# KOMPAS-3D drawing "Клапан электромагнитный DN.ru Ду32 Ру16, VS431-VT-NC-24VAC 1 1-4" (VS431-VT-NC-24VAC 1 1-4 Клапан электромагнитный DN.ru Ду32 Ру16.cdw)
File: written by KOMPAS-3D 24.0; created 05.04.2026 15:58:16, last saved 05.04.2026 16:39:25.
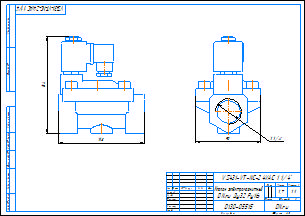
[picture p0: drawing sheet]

Document properties: c3d_UniqueCompID: ef56311e-7521-43dc-8291-0e6108b3d81d; Автор: artio; Класс точности: c; Знак неуказанной шероховатости: Шероховатость не задана; Рассекать на разрезах: Да; c3d_UniqueCompID: ef56311e-7521-43dc-8291-0e6108b3d81d; Автор: artio; Класс точности: c; Знак неуказанной шероховатости: Шероховатость не задана; Рассекать на разрезах: Да; c3d_UniqueCompID: ef56311e-7521-43dc-8291-0e6108b3d81d; Автор: artio; Класс точности: c; Знак неуказанной шероховатости: Шероховатость не задана; Рассекать на разрезах: Да; Автор: artio; Форматы листов документа: A3; Полное имя файла: VS431-VT-NC-24VAC 1 1-4 Клапан электромагнитный DN.ru Ду32 Ру16.m3d; Масса: 1.701; Наименование: Клапан электромагнитный DN.ru Ду32 Ру16; Количество листов документа: 1; Примечание: D130-05515

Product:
- Body: Тело 1  | qty 1
    Масса: 3.709873
- Part/product: Клапан электромагнитный DN.ru Ду32 Ру16  | designation VS431-VT-NC-24VAC 1 1-4
    Масса: 1.701
    Раздел спецификации: Прочие изделия
    Примечание: D130-05515
    additional columns: ef56311e-7521-43dc-8291-0e6108b3d81d; artio; c; Шероховатость не задана; Да

Views: Вид 1, Спереди
Referenced files in C:\Users\artio\OneDrive\Рабочий стол\Клапан электромагнитный DN.ru\VS431\VS431-ET-NC\: VS431-ET-NC-24VAC 3-4 Клапан электромагнитный DN.ru Ду20 Ру16.m3d, VS431-ET-NC-24VAC 3-4 Клапан электромагнитный DN.ru Ду20 Ру16.cdw
Referenced files in C:\Users\artio\OneDrive\Рабочий стол\Клапан электромагнитный DN.ru\VS431\VS431-VT-NC\: VS431-VT-NC-24VAC 1 1-4 Клапан электромагнитный DN.ru Ду32 Ру16.m3d
Referenced files in C:\Users\artio\OneDrive\Рабочий стол\Клапан электромагнитный DN.ru\VS431\VS431-VT-NC\VS431-VT-NC-24VAC\Ду32\: VS431-VT-NC-24VAC 1 1-4 Клапан электромагнитный DN.ru Ду32 Ру16.m3d
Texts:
  VS431-VT-NC-24VAC 1 1-4
  Клапан электромагнитный
  DN.ru Ду32 Ру16
  VS431-VT-NC-24VAC 1 1/4"
  VS431-VT-NC-24VAC 1 1/4"-
  Клапан электромагнитный DN.ru Ду32 Ру16
  VS431-VT-NC-24VAC 1 1-4 Клапан электромагнитный DN.ru Ду32 Ру16
Dimensions and other numbers on the sheet: 0; 3; 2; 4; 90; 1 1/4"; 1:1; 1; 1,7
